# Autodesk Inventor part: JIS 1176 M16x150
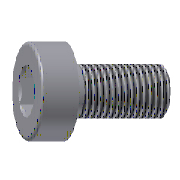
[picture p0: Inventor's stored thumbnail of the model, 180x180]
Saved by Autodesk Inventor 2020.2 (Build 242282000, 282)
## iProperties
Created: 2019-01
Part Number: JIS 1176 M16x150
Material: Stal, miękka
Description: Wkręt z łbem półkolistym walcowym
Document SubType Name: Modeling
Designer: F.Stasiak
Standard Revision: 1
Language: pl-PL
Size Designation: M16x150
Categories: <MemberInstance><Categories><Category DisplayName="Forma wtryskowa" InternalName="349578f2-f4d4-4954-8c09-8e99297a61c0" Mnemonic="MOLD"><Category DisplayName="C
Mass: 0.133121 g
Surface Area: 2.01441 cm^2
Volume: 0.133121 cm^3
Density: 7.85 g/cm^3
Appearance: Częściowo polerowany
Catalog Web Link: www.expertbooks.pl
Manager: www.cadconsulting.pl
Company: Fabian Stasiak CAD Consulting
IsCustomPart: 0
Author: F.Stasiak
Subject: Zbiór ćwiczeń. Autodesk Inventor 2020. Kurs Professional
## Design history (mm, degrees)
body "Solid1"
revolve "Obrót1" stored, may be unused: angle "d44" = 90 deg
sketch "Sketch2"
  geometry: L1 (0, 8.083)-(7, 4.041); L2 (7, 4.041)-(7, -4.041); L3 (7, -4.041)-(0, -8.083); L4 (0, -8.083)-(-7, -4.041); L5 (-7, -4.041)-(-7, 4.041); L6 (-7, 4.041)-(0, 8.083); 3 further points
  constraints: 12 end point, 2 vertical alignment, 1 coincident, 14 other
extrude "Wyciągnięcie proste1" cut sketch "Sketch2" taper "d9" = 0 deg; stored distance "d45" = 10
feature "Gwint1" dims "d10" = 44 (= b), "d11" = 0
chamfer "Faza1" distance "d12" = 1 (= 0.5 x P); stored, may be unused: second distance "d50" = 2, angle "d51" = 45 deg
fillet "Zaokrąglenie1" dims "d13" = 1 (= 0.5 x P)
sketch "Sketch1"
  geometry: L1 (0, -183.2)-(0, 49.2) reference; L2 (8.083, 16)-(12, 16); L3 (12, 16)-(12, 0); L4 (12, 0)-(8, 0); L5 (8, 0)-(8, -150); L6 (8, -150)-(0, -150); L7 (0, 3.794)-(0, -150); L8 (0, 3.794)-(7, 8); L9 (7, 8)-(7, 14.917); L10 (7, 14.917)-(8.083, 16); 1 further point
  constraints: 18 end point, 4 vertical, 3 horizontal, 2 point on line
  dimensions: "d0" = 24 diameter of L3 L1 (= dk); "d1" = 16 distance between parallel lines of L4 L2 (= k); "d2" = 16 diameter of L5 L1 (= d); "d3" = 150 distance between parallel lines of L6 L4 (= L); "d4" = 59 deg angle of L1 L8; "d5" = 45 deg angle of L1 L10; "d6" = 14 diameter of L9 L1 (= sw); "d7" = 16.16581 diameter of L2.start L1 (= 1.1547 x sw); "d8" = 8 distance from line of L8.end L2 (= t)
other parameters: "d" = 16 [user parameter; used in 1 equation term], "L" = 150 [user parameter; used in 1 equation term], "dk" = 24 [user parameter; used in 1 equation term], "b" = 44 [user parameter; used in 1 equation term], "k" = 16 [user parameter; used in 1 equation term], "sw" = 14 [user parameter; used in 2 equation terms], "t" = 8 [user parameter; used in 1 equation term], "P" = 2 [user parameter; used in 2 equation terms], "d14" = 0, "d15" = 0, "d55" = 0
